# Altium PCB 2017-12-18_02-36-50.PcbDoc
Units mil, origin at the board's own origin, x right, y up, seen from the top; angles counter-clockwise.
Board outline 2206 x 2006 mil, 4 copper layers (Top Layer, MidLayer1, MidLayer2, Bottom Layer); 12 components, 6 nets, 34 pads, 31 vias.
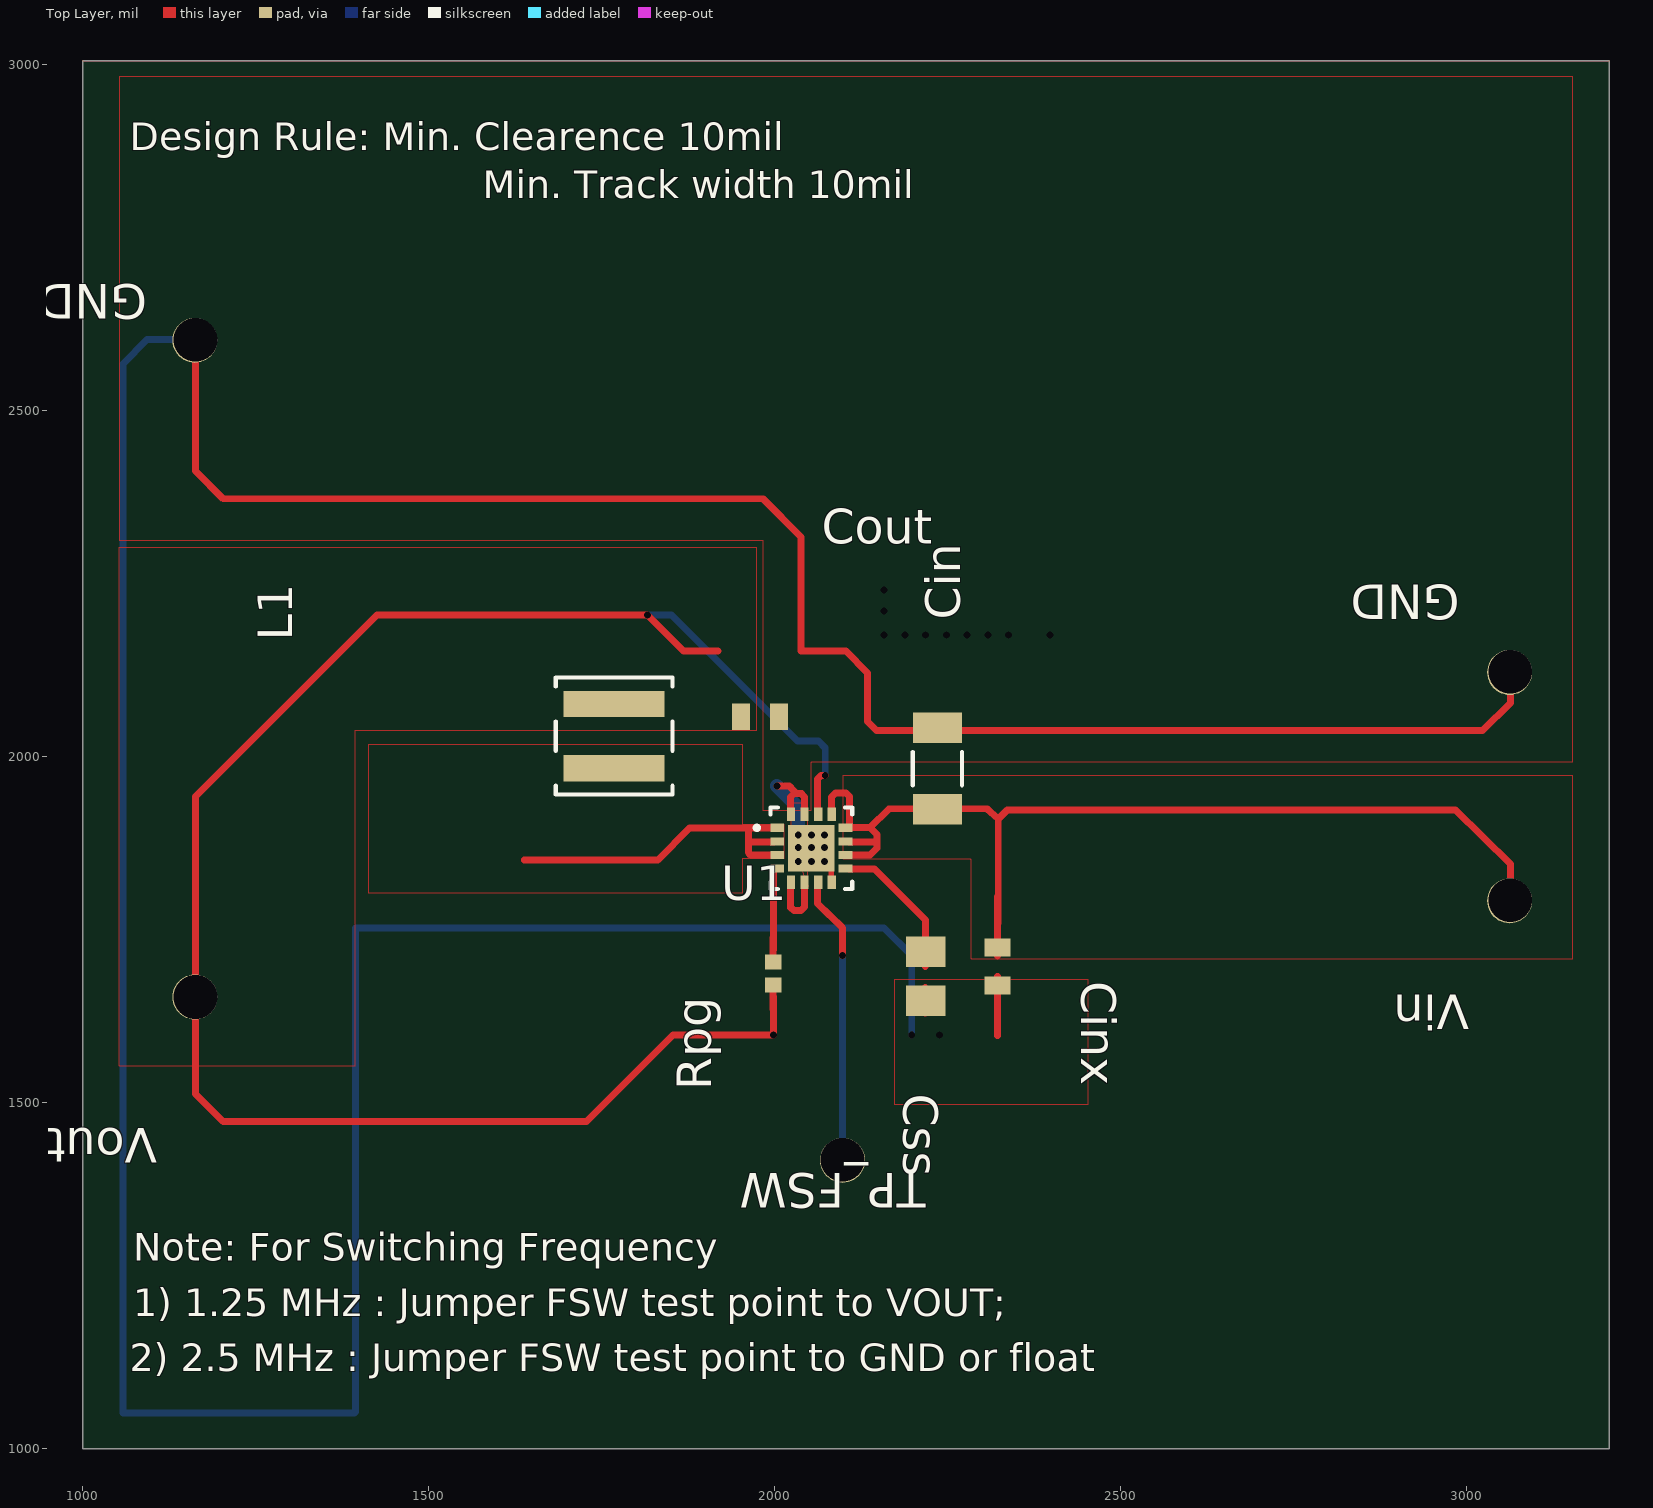
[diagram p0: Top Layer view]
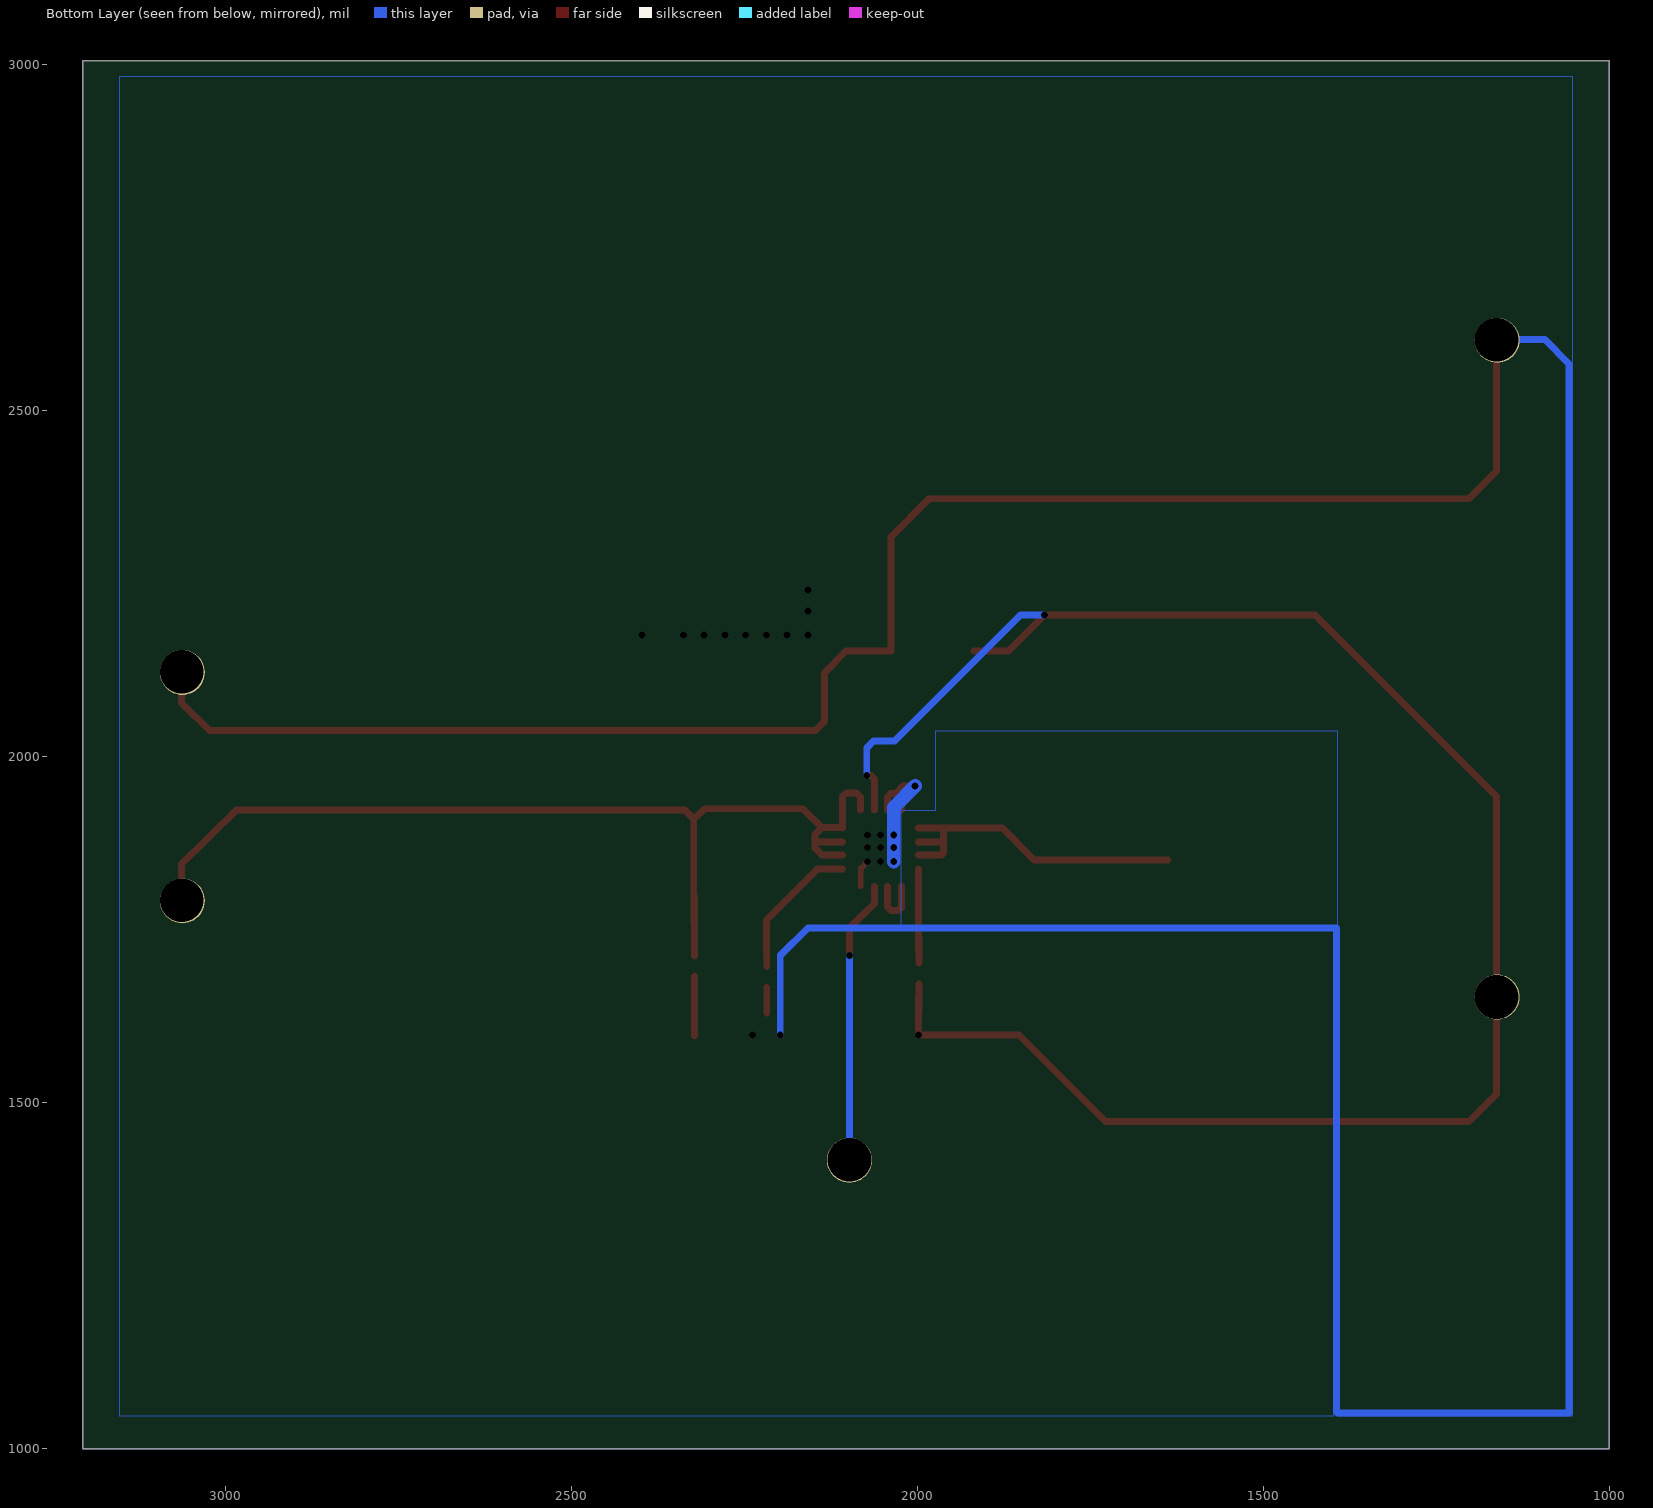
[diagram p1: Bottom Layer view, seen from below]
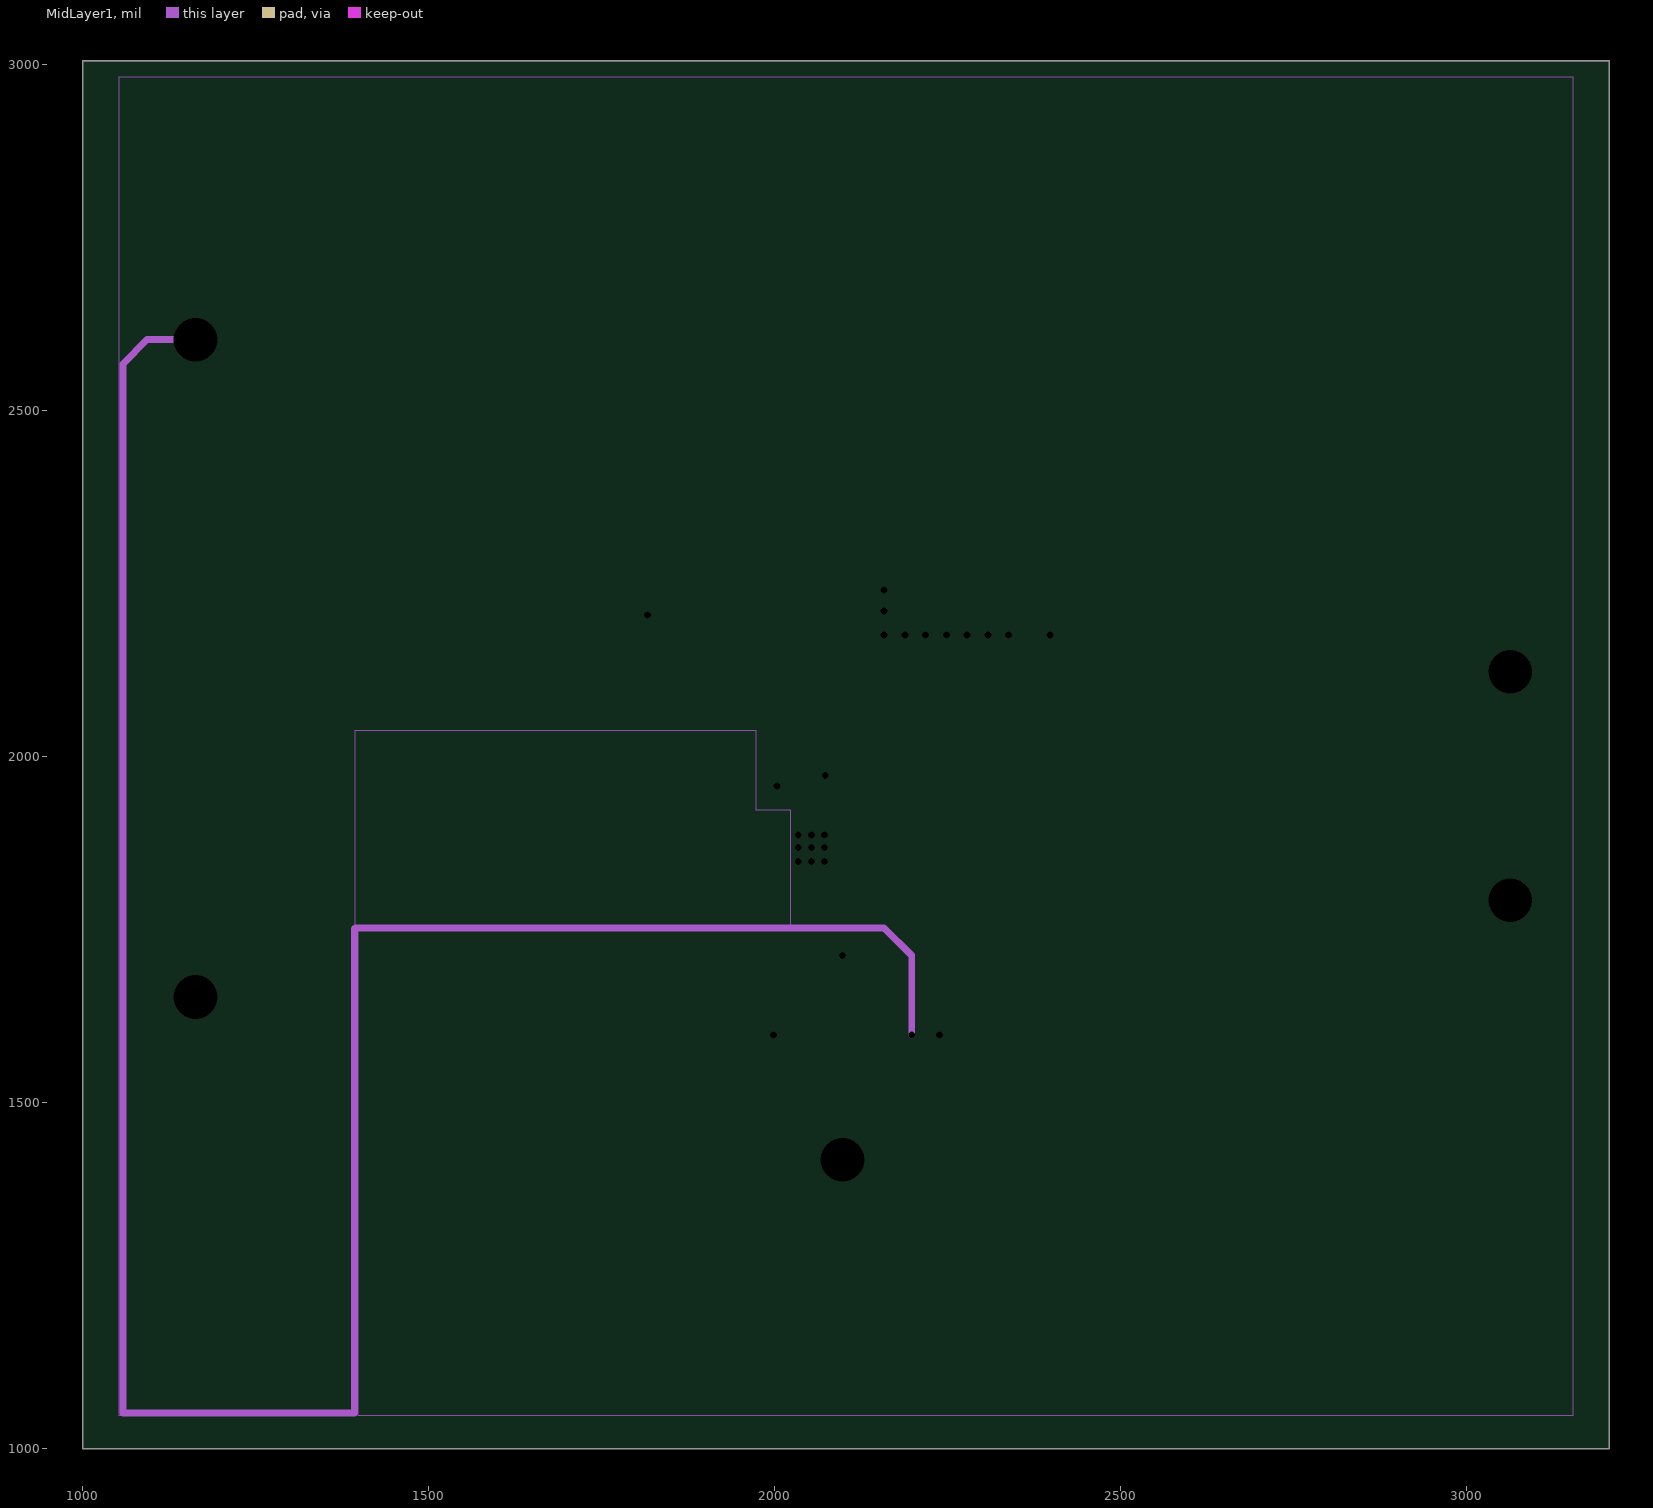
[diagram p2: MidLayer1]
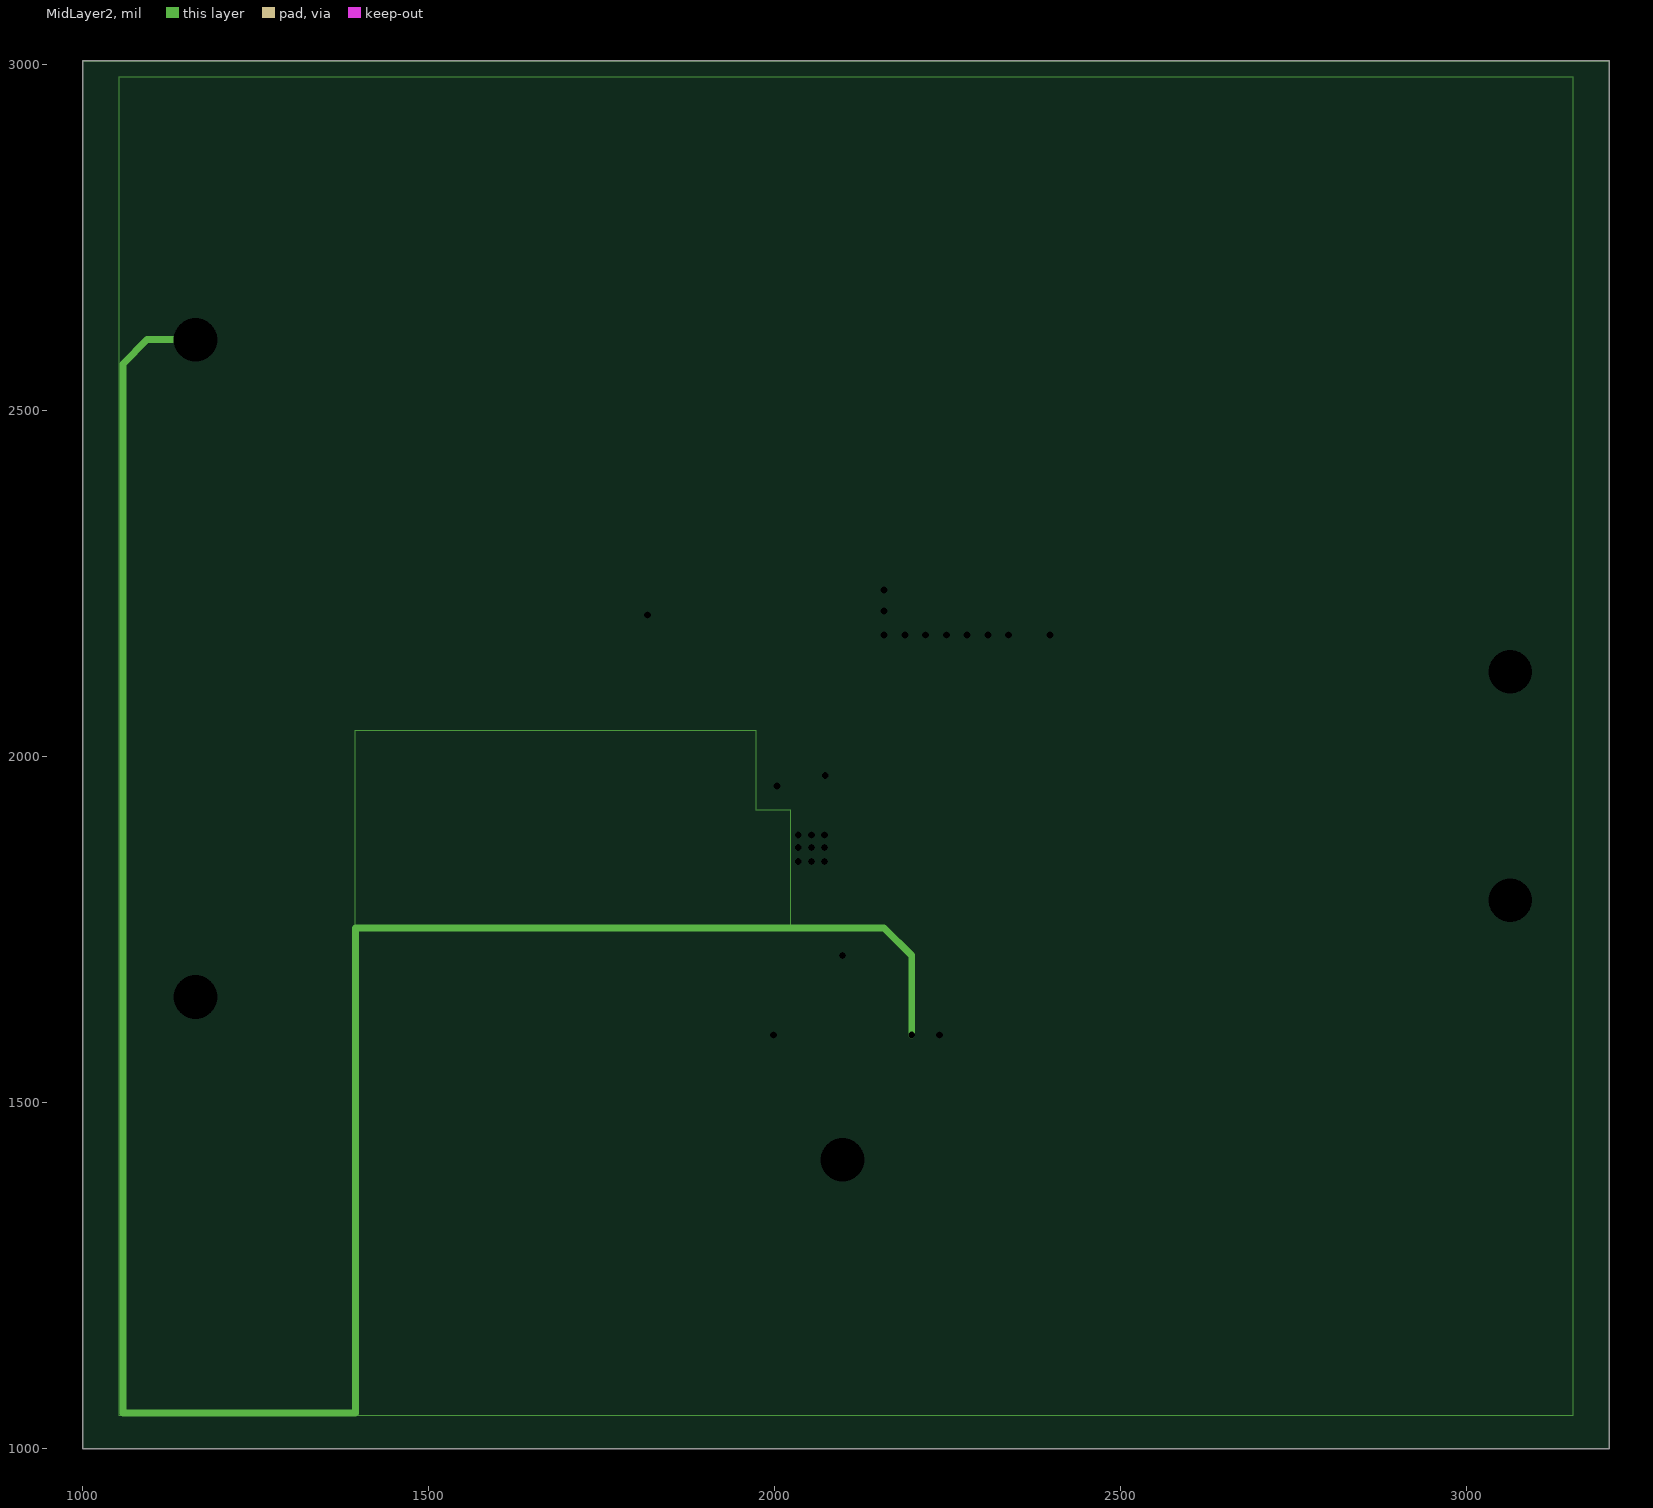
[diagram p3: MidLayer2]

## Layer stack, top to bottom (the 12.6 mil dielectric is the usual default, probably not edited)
Top Layer: signal copper 1.4
Dielectric: core 12.6, FR-4, Dk 4.8
MidLayer1: signal copper 1.4
Dielectric: prepreg 12.6, FR-4, Dk 4.8
MidLayer2: signal copper 1.4
Dielectric: core 12.6, FR-4, Dk 4.8
Bottom Layer: signal copper 1.4

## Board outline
1000,1000 3206,1000 3206,3006 1000,3006

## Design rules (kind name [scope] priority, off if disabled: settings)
PlaneConnect [All] p0: scope1count=1 scope1_0_kind=Board scope1_0_value=Board scope2count=1 scope2_0_kind=Board scope2_0_value=Board commentlength=0 planeconnectstyle=Direct reliefexpansion=20 reliefentries=4 reliefconductorwidth=10 reliefairgap=10
PlaneConnect [All] p1: planeconnectstyle=Direct reliefexpansion=20 reliefentries=4 reliefconductorwidth=10 reliefairgap=10
PolygonConnect [All] p0: scope1count=1 scope1_0_kind=Board scope1_0_value=Board scope2count=1 scope2_0_kind=Board scope2_0_value=Board commentlength=0 connectstyle=Direct reliefconductorwidth=10 reliefentries=4 polygonreliefangle="90 Angle"
PolygonConnect [All] p1: connectstyle=Direct reliefconductorwidth=10 reliefentries=4 polygonreliefangle="90 Angle"

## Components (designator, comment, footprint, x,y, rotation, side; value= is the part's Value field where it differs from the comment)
Cin "" 1206_190 2235,1983 r90 top
Cinx "" 0603 2322,1697 r270 top
Cout "" 0603 1979,2058 r0 top
Css "" 0805 2218,1683 r270 top
GND "" TP-1502 3062,2122 r180 top
GND1 "" TP-1502 1162,2602 r180 top
L1 "" XAL4020 1768,2030 r90 top
Rpg "" 0402 1998,1687 r90 top
TP_FSW "" TP-1502 2098,1417 r180 top
U1 "" S-PVQFN-N16 2053,1868 r0 top
Vin "" TP-1502 3062,1792 r180 top
Vout "" TP-1502 1162,1653 r180 top

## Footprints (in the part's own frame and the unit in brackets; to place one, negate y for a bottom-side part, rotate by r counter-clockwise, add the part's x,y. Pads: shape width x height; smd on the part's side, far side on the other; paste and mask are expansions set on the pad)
0402 [mil]
  rect 22x24 smd: 1(-16.5,0) 2(16.5,0)
0603 [mil]
  rect 26x38 smd: 1(-27.5,0) 2(27.5,0)
0805 [mil]
  rect 44x57 smd: 1(-35.5,0) 2(35.5,0)
1206_190 [mil]
  rect 44x71 smd: 1(-59,0) 2(59,0)
  silkscreen extent -24,-36 24,36
S-PVQFN-N16 [mm]
  rect 0.5x0.3 smd: 1(-1.25,0.75) 2(-1.25,0.25) 3(-1.25,-0.25) 4(-1.25,-0.75) 9(1.25,-0.75) 10(1.25,-0.25) 11(1.25,0.25) 12(1.25,0.75)
  rect 0.3x0.5 smd: 5(-0.75,-1.25) 6(-0.25,-1.25) 7(0.25,-1.25) 8(0.75,-1.25) 13(0.75,1.25) 14(0.25,1.25) 15(-0.25,1.25) 16(-0.75,1.25)
  rect 1.7x1.7 smd: 17(0,0)
  silkscreen extent -2.08,-1.5 1.5,1.5
TP-1502 [mil]
  round 65 / inner round 0 / far side round 65 hole 32: 1(0,0)
XAL4020 [mil]
  rect 38x146 smd: 1(-46.5,0) 2(46.5,0)
  silkscreen extent -84,-84 84,84

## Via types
v1: diameter 0, hole 10, Top Layer to Bottom Layer, 26 vias
v2: diameter 0, hole 63, Top Layer to Bottom Layer, 5 vias

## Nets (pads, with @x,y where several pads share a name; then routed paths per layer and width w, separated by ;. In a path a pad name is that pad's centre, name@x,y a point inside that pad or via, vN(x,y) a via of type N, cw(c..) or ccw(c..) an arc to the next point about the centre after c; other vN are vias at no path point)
0: Cin.2 Cinx.2 Cout.2 Css.2 GND1.1 GND.1 U1.5 U1.6 U1.8 U1.15 U1.16 U1.17 | length 13729.6
  Top Layer w8: v1(2072,1849) U1.17@2081,1839 ; U1.8@2082,1813 U1.17@2082,1839
  Top Layer w10: v2(1163,2603) 1163,2413 1203,2373 1983,2373 2038,2318 2038,2153 2103,2153 2134,2121 2134,2051 2147,2038 3023,2038 3063,2078 v2(3063,2123) ; v1(2003,1958) 2021,1958 2028,1951 2028,1947 ; U1.5@2023,1813 2023,1782 2028,1778 2038,1778 2043,1783 2043,1812 U1.6@2043,1813 ; U1.16@2023,1923 2023,1942 2028,1947 ; U1.15@2043,1923 2043,1942 2039,1947 2028,1947 ; Css.2@2217.5,1630 Css.2@2217.5,1667 ; 2322,1597 2322,1683
  MidLayer1 w10: v2(1163,2603) 1093,2603 1058,2568 1058,1052 1393,1052 1393,1752 1394,1753 2158,1753 2198,1713 v1(2198,1598)
  MidLayer2 w10: v2(1163,2603) 1093,2603 1058,2568 1058,1052 1394,1052 1394,1753 2158,1753 2198,1713 v1(2198,1598)
  Bottom Layer w10: v2(1163,2603) 1093,2603 1058,2568 1058,1052 1393,1052 ; 1394,1053 1394,1753 2158,1753 2198,1713 v1(2198,1598)
  Bottom Layer w20: v1(2003,1958) 2034,1927 v1(2034,1887) v1(2034,1849)
  other v1: 2238,1598 2053,1849 2034,1869 2053,1869 2072,1869 2053,1887 2072,1887 2158,2176 2188,2176 2218,2176 2248,2176 2278,2176 2308,2176 2338,2176 2398,2176 2158,2211 2158,2241
1: Cin.1 Cinx.1 U1.10 U1.11 U1.12 U1.13 Vin.1 | length 1512.4
  Top Layer w10: U1.13@2082,1923 2082,1942 2088,1948 2103,1948 2108,1943 2108,1897 2108,1898 2138,1898 ; U1.10@2108,1858 2138,1858 2148,1868 2148,1877 ; U1.11@2108,1877 2148,1877 ; Cinx.1@2322,1712 2322,1798 ; 2323,1760 2323,1910 ; v2(3063,1793) 3063,1845 2984,1923 2336,1923 2323,1910 ; 2138,1898 2148,1888 2148,1877 ; 2138,1898 2165,1925 2233,1925 2307,1925 2323,1910
2: Css.1 U1.9 | length 225.7
  Top Layer w10: U1.9@2108,1838 2144,1838 2218,1764 Css.1@2218,1716 ; Css.1@2217.5,1697 Css.1@2217.5,1734
3: Cout.1 L1.2 Rpg.1 TP_FSW.1 U1.7 U1.14 Vout.1 | length 3156.2
  Top Layer w10: 1918,2153 1868,2153 v1(1816,2205) 1638,2205 1425,2205 1163,1943 v2(1163,1653) 1163,1513 1203,1473 1728,1473 1853,1598 v1(1998,1598) 1998,1654 ; 1997.5,1635 Rpg.1@1997.5,1672 ; U1.7@2062,1813 2062,1788 2098,1753 v1(2098,1713) ; U1.14@2062,1923 2062,1968 2067,1973 v1(2073,1973)
  Bottom Layer w10: v1(1816,2205) 1851,2205 2033,2023 2063,2023 2073,2013 v1(2073,1973) ; v2(2098,1418) v1(2098,1713)
4: Rpg.2 U1.4 | length 154
  Top Layer w10: Rpg.2@1997.5,1702 1997.5,1739 ; 1998,1721 U1.4@1998,1838
5: L1.1 U1.1 U1.2 U1.3 | length 488.9
  Top Layer w10: 1638,1851 1831,1851 1877,1897 1964,1897 ; U1.3@1998,1858 1965,1858 1962,1862 1962,1877 ; U1.2@1998,1877 1962,1877 ; U1.1@1998,1897 1964,1897 ; 1962,1877 1962,1895 1964,1897

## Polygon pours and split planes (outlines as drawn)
5 on Top Layer " " (solid, pour order 0): 2013,1853 1953,1853 1953,1803 1413,1803 1413,2018 1953,2018 1953,1903 2013,1903
3 on Top Layer " " (solid, pour order 1): 1053,2303 1973,2303 1973,2038 1393,2038 1393,1553 1053,1553
1 on Top Layer " " (solid, pour order 2): 2098,1853 2283,1853 2283,1708 3153,1708 3153,1973 2098,1973
0 on Top Layer " " (solid, pour order 6): 2453,1678 2173,1678 2173,1498 2453,1498
0 on Top Layer " " (solid, pour order 7): 2048,1838 2083,1838 2083,1898 2048,1898 2048,1933 2023,1933 2023,1838 2038,1838 2048,1813
0 on Top Layer " " (solid, pour order 8): 2053,1993 3153,1993 3153,2983 1053,2983 1053,2313 1983,2313 1983,1923 2053,1923 2053,1953
0 on Bottom Layer " " (solid, pour order 4): 1973,1923 1973,2038 1393,2038 1393,1048 1053,1048 1053,2983 3153,2983 3153,1048 1398,1048 1398,1753 2023,1753 2023,1923
0 on MidLayer1 " " (solid, pour order 3): 1973,1923 1973,2038 1393,2038 1393,1048 1053,1048 1053,2983 3153,2983 3153,1048 1398,1048 1398,1753 2023,1753 2023,1923
0 on MidLayer2 " " (solid, pour order 5): 1973,1923 1973,2038 1393,2038 1393,1048 1053,1048 1053,2983 3153,2983 3153,1048 1398,1048 1398,1753 2023,1753 2023,1923

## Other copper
Multi-Layer:
  the board outline again, w1

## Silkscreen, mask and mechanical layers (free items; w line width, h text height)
Top Overlay:
  text "Design Rule: Min. Clearence 10mil" at 1068,2877 h40
  text "Min. Track width 10mil" at 1578,2807 h40
  text "Note: For Switching Frequency" at 1073,1272 h40
  text "1) 1.25 MHz : Jumper FSW test point to VOUT;" at 1073,1192 h40
  text "2) 2.5 MHz : Jumper FSW test point to GND or float" at 1068,1112 h40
